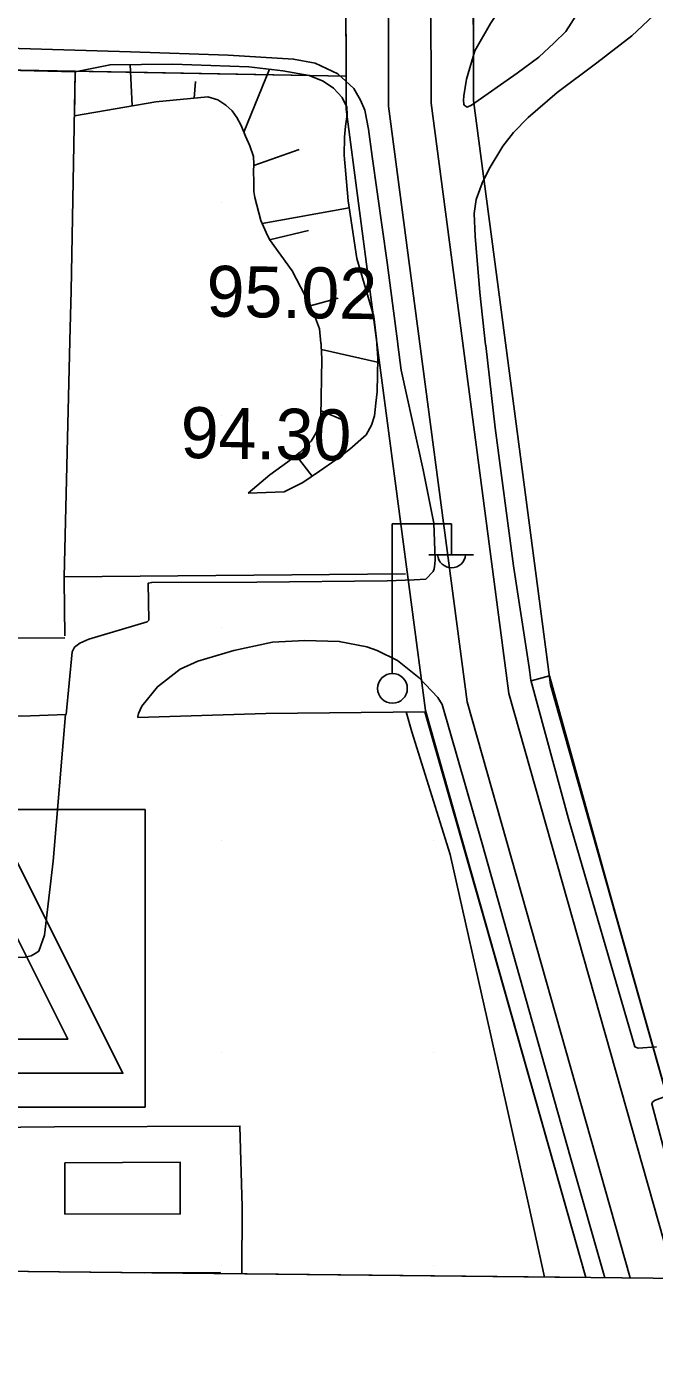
# Model space of a CAD drawing. Extents: x 417995 to 421451, y 4454518 to 4458015.
# Drawn here: x 420398.8 to 420472.7, y 4454999.4 to 4455155 of the extents above; entities that cross this region are included whole.
import ezdxf

# ---------------------------------------------------------------- set-up
doc = ezdxf.new("R2010")
doc.units = 0
for name, color, linetype in [('ADAKENARI', 7, 'Continuous'), ('B_Betonzemin', 7, 'Continuous'), ('B_Kapi', 7, 'Continuous'), ('B_Spor_Tesisleri', 7, 'Continuous'), ('KALDIRIM_FAT', 7, 'Continuous'), ('PAFTALAMA', 7, 'Continuous'), ('PL_AYA_PARK_DINLENME', 7, 'Continuous'), ('PL_EĞİTİM', 7, 'Continuous'), ('PL_KAMU_HİZMET_ALANI', 7, 'Continuous'), ('S_Elektrik_Diregi', 7, 'Continuous'), ('SEMBOL_FAT', 7, 'Continuous'), ('Sev_Sevalti', 7, 'Continuous'), ('Sev_Sevustu', 7, 'Continuous'), ('Sev_Tarama', 7, 'Continuous'), ('Sinir_Duvar_tek_tarafa_ait', 7, 'Continuous'), ('Sinir_Ist_Duvari', 7, 'Continuous'), ('Sinir_Tel_bir_taraf', 7, 'Continuous'), ('TRFAT_EĞİTİM', 7, 'Continuous'), ('TRFAT_PARKALANI', 7, 'Continuous'), ('Y_Kot_Noktasi', 7, 'Continuous'), ('Y_Lejant', 7, 'Continuous'), ('Yol_Kaldirim_kenari_bordurtasi', 7, 'Continuous'), ('Yol_Sose', 7, 'Continuous'), ('Yol_Toprak_Duz', 7, 'Continuous'), ('Yol_Toprak_Kesik', 7, 'Continuous')]:
    doc.layers.add(name, color=color, linetype=linetype)

msp = doc.modelspace()

# ---------------------------------------------------------------- linework, layer by layer
at = {"layer": 'ADAKENARI'}
for p, q in [((420451.44, 4455146.33), (420451.28, 4455217.73)), ((420436.41, 4455159.21), (420436.44, 4455149.21)), ((420315.15, 4455151.42), (420436.44, 4455149.21)), ((420436.44, 4455149.21), (420436.45, 4455145.33)), ((420436.45, 4455145.33), (420439.36, 4455123.19)), ((420454.49, 4455123.19), (420451.44, 4455146.33)), ((420439.36, 4455123.19), (420445.76, 4455074.56)), ((420460.48, 4455077.61), (420454.49, 4455123.19)), ((420480.29, 4455007.71), (420460.48, 4455077.61)), ((420445.76, 4455074.56), (420464.66, 4455007.88))]:
    msp.add_line(p, q, dxfattribs=at)
at = {"layer": 'B_Betonzemin'}
for points in [[(420403.4, 4455074.09), (420401.93, 4455056.87), (420400.94, 4455048.14), (420400.26, 4455046.28), (420399.84, 4455045.99), (420399.36, 4455045.7), (420398.67, 4455045.55), (420375.88, 4455045.37), (420375.61, 4455073.76)], [(420443.49, 4455074.4), (420444.17, 4455072.08), (420448.68, 4455057.65), (420453.42, 4455036.53), (420457.92, 4455016.5), (420459.8, 4455007.93)]]:
    msp.add_lwpolyline(points, dxfattribs=at)
at = {"layer": 'B_Kapi'}
msp.add_lwpolyline([(420403.34, 4455083.37), (420403.23, 4455089.9)], dxfattribs=at)
at = {"layer": 'B_Spor_Tesisleri'}
msp.add_lwpolyline([(420403.34, 4455015.33), (420403.33, 4455021.36), (420416.88, 4455021.45), (420416.9, 4455015.35)], close=True, dxfattribs=at)
msp.add_lwpolyline([(420412.71, 4455008.42), (420421.59, 4455008.48), (420421.59, 4455008.33)], dxfattribs=at)
at = {"layer": 'KALDIRIM_FAT'}
for p, q in [((420441.44, 4455145.66), (420441.28, 4455218.18)), ((420446.44, 4455146), (420446.28, 4455217.95)), ((420444.57, 4455121.88), (420441.44, 4455145.66)), ((420449.53, 4455122.54), (420446.44, 4455146)), ((420450.67, 4455075.58), (420444.57, 4455121.88)), ((420455.58, 4455076.59), (420449.53, 4455122.54)), ((420469.87, 4455007.82), (420450.67, 4455075.58)), ((420475.08, 4455007.77), (420455.58, 4455076.59))]:
    msp.add_line(p, q, dxfattribs=at)
at = {"layer": 'PAFTALAMA'}
msp.add_line((419138.44, 4455021.89), (421266.41, 4454999.4), dxfattribs=at)
at = {"layer": 'PL_AYA_PARK_DINLENME'}
msp.add_lwpolyline([(420323.63, 4455163.96), (420336.03, 4455233.44), (420344.03, 4455277.38), (420370.39, 4455328), (420388.66, 4455320.38), (420456.9, 4455291.9), (420456.9, 4455291.9), (420439.12, 4455249.29), (420436.28, 4455218.4), (420436.36, 4455181.21), (420436.41, 4455161.21), (420436.41, 4455159.21), (420436.44, 4455149.21), (420315.15, 4455151.42)], close=True, dxfattribs=at)
at = {"layer": 'PL_EĞİTİM'}
for p, q in [((420345.26, 4455009.14), (420464.66, 4455007.88)), ((420464.66, 4455007.88), (420345.26, 4455009.14))]:
    msp.add_line(p, q, dxfattribs=at)
msp.add_lwpolyline([(420464.66, 4455007.88), (420445.76, 4455074.56), (420439.36, 4455123.19), (420436.45, 4455145.33), (420436.44, 4455149.21), (420315.15, 4455151.42), (420296.75, 4455124.2), (420271.71, 4455086.83), (420279.66, 4455086.21), (420282.64, 4455090.54), (420329.76, 4455089.97), (420344.76, 4455089.79), (420345.26, 4455009.14)], dxfattribs=at)
at = {"layer": 'PL_KAMU_HİZMET_ALANI'}
msp.add_lwpolyline([(420608.01, 4455006.36), (420610.24, 4455191.26), (420611.77, 4455234.39), (420452.99, 4455236.3), (420451.28, 4455217.73), (420451.44, 4455146.33), (420454.49, 4455123.19), (420460.48, 4455077.61), (420480.29, 4455007.71)], dxfattribs=at)
at = {"layer": 'S_Elektrik_Diregi'}
for p, q in [((420441.85, 4455079.02), (420441.85, 4455096.52)), ((420441.85, 4455096.52), (420448.85, 4455096.52)), ((420448.85, 4455093.02), (420448.85, 4455096.52)), ((420446.19, 4455092.88), (420451.44, 4455092.88))]:
    msp.add_line(p, q, dxfattribs=at)
msp.add_circle((420441.89, 4455077.18), 1.75, dxfattribs=at)
msp.add_arc((420448.85, 4455093.03), 1.66, 184.8384, 355.1464, dxfattribs=at)
at = {"layer": 'SEMBOL_FAT'}
for p, q in [((420377.78, 4455062.91), (420412.78, 4455062.91)), ((420412.78, 4455062.91), (420412.78, 4455027.91)), ((420377.78, 4455027.91), (420412.78, 4455027.91))]:
    msp.add_line(p, q, dxfattribs=at)
msp.add_lwpolyline([(420395.28, 4455061.53), (420395.28, 4455052.61), (420386.89, 4455035.91), (420403.66, 4455035.91), (420395.28, 4455052.61), (420395.28, 4455061.53), (420410.15, 4455031.91), (420380.41, 4455031.91)], close=True, dxfattribs=at)
at = {"layer": 'Sev_Sevalti'}
for points in [[(420404.44, 4455144.51), (420404.53, 4455149.71), (420408.65, 4455150.54), (420416.03, 4455150.6), (420425, 4455150.31), (420428.98, 4455149.83), (420432.08, 4455149.27), (420433.74, 4455148.6), (420434.93, 4455147.78), (420435.97, 4455146.7), (420436.5, 4455145.55), (420436.54, 4455144.7), (420436.37, 4455143.32), (420436.25, 4455142.03), (420436.22, 4455139.91), (420436.69, 4455134.53), (420437.68, 4455127.74)], [(420437.68, 4455127.74), (420439.7, 4455120.92), (420440.02, 4455118.25), (420440.05, 4455117.72)], [(420440.06, 4455117.65), (420440.15, 4455116.02), (420440.1, 4455112.08), (420439.95, 4455110.71), (420439.78, 4455109.24), (420439.42, 4455108.16), (420438.78, 4455107.02), (420436.87, 4455105.31), (420435.21, 4455104.06), (420433.29, 4455102.74), (420431.34, 4455101.38), (420429.13, 4455100.31), (420424.91, 4455100.16)], [(420440.05, 4455117.72), (420440.06, 4455117.65)]]:
    msp.add_lwpolyline(points, dxfattribs=at)
at = {"layer": 'Sev_Sevustu'}
for points in [[(420433.47, 4455117.79), (420433.29, 4455119.48), (420432.82, 4455120.71), (420432.09, 4455122.45), (420430.09, 4455126.3), (420427.4, 4455129.97), (420427.01, 4455130.79), (420426.4, 4455132.23), (420425.7, 4455134.94), (420425.58, 4455135.64), (420425.57, 4455136.83), (420425.55, 4455137.93), (420425.56, 4455138.83), (420425.53, 4455139.75), (420425.08, 4455141), (420424.6, 4455142.12), (420424.08, 4455143.39), (420423.57, 4455144.35), (420423.02, 4455145.11), (420422.27, 4455145.8), (420421.34, 4455146.4), (420420.14, 4455146.75), (420414.05, 4455146.18), (420404.44, 4455144.51)], [(420424.91, 4455100.16), (420427.46, 4455102.29), (420429.57, 4455103.82), (420431.04, 4455104.96), (420432.32, 4455106.24), (420432.93, 4455107.31), (420433.47, 4455109.16), (420433.58, 4455115.91), (420433.5, 4455117.52), (420433.48, 4455117.72), (420433.47, 4455117.79)]]:
    msp.add_lwpolyline(points, dxfattribs=at)
at = {"layer": 'Sev_Tarama'}
for p, q in [((420411.24, 4455145.69), (420411.02, 4455150.56)), ((420424.4, 4455142.61), (420427.4, 4455150.02)), ((420418.56, 4455146.6), (420418.7, 4455148.55)), ((420425.56, 4455138.7), (420430.92, 4455140.57)), ((420426.55, 4455131.87), (420436.81, 4455133.71)), ((420427.41, 4455129.96), (420432.02, 4455131.05)), ((420432.21, 4455122.17), (420435.49, 4455123.1)), ((420433.53, 4455117.04), (420440.14, 4455115.57)), ((420433.48, 4455109.83), (420436.27, 4455108.67)), ((420430.56, 4455104.59), (420432.45, 4455102.15))]:
    msp.add_line(p, q, dxfattribs=at)
at = {"layer": 'Sinir_Duvar_tek_tarafa_ait'}
for points in [[(420328.79, 4455129.16), (420328.85, 4455151.54), (420404.53, 4455149.71), (420404.06, 4455123.96)], [(420404.06, 4455123.96), (420403.92, 4455118.1)], [(420403.34, 4455083.12), (420373.18, 4455082.92), (420344.61, 4455082.79), (420344.58, 4455089.9), (420328.97, 4455090.19), (420328.84, 4455118.82)], [(420403.92, 4455118.03), (420403.24, 4455090.31), (420403.23, 4455089.9)], [(420403.92, 4455118.1), (420403.92, 4455118.03)]]:
    msp.add_lwpolyline(points, dxfattribs=at)
at = {"layer": 'Sinir_Ist_Duvari'}
for points in [[(420443.43, 4455090.64), (420403.24, 4455090.31)], [(420445.7, 4455074.43), (420452.81, 4455049.64), (420464.64, 4455007.87)]]:
    msp.add_lwpolyline(points, dxfattribs=at)
at = {"layer": 'Sinir_Tel_bir_taraf'}
for points in [[(420346.07, 4455073.62), (420369.8, 4455073.69), (420390.78, 4455073.94), (420398.2, 4455073.89), (420403.49, 4455074.1)], [(420411.9, 4455073.74), (420426.99, 4455074.21), (420445.7, 4455074.43)]]:
    msp.add_lwpolyline(points, dxfattribs=at)
at = {"layer": 'TRFAT_EĞİTİM'}
for p, q in [((420421.71, 4455134.33), (420421.71, 4455134.33)), ((420421.71, 4455109.33), (420421.71, 4455109.33)), ((420421.71, 4455084.33), (420421.71, 4455084.33)), ((420421.71, 4455059.33), (420421.71, 4455059.33)), ((420446.71, 4455059.33), (420446.71, 4455059.33)), ((420421.71, 4455034.33), (420421.71, 4455034.33)), ((420446.71, 4455034.33), (420446.71, 4455034.33)), ((420421.71, 4455009.33), (420421.71, 4455009.33)), ((420446.71, 4455009.33), (420446.71, 4455009.33))]:
    msp.add_line(p, q, dxfattribs=at)
at = {"layer": 'TRFAT_PARKALANI'}
for p, q in [((420400.99, 4455153.17), (420400.99, 4455153.17)), ((420431.88, 4455149.48), (420431.88, 4455149.48))]:
    msp.add_line(p, q, dxfattribs=at)
at = {"layer": 'Y_Lejant'}
msp.add_lwpolyline([(419168.18, 4457798.01), (421295.36, 4457775.52), (421266.41, 4454999.4), (419138.44, 4455021.89)], close=True, dxfattribs=at)
at = {"layer": 'Yol_Kaldirim_kenari_bordurtasi'}
for points in [[(420472.59, 4455034.98), (420467.84, 4455051.8), (420460.39, 4455078.64), (420458.2, 4455078.08)], [(420424.14, 4455008.3), (420424.2, 4455016.2), (420423.94, 4455025.68), (420402.09, 4455025.61), (420374.43, 4455025.33), (420355.49, 4455025.39), (420355.57, 4455009.03)]]:
    msp.add_lwpolyline(points, dxfattribs=at)
at = {"layer": 'Yol_Sose'}
for points in [[(420456.13, 4455091.59), (420457.98, 4455079.65), (420458.18, 4455078.14)], [(420403.49, 4455074.1), (420404.17, 4455081.48), (420404.44, 4455082.01), (420405.08, 4455082.51), (420406.15, 4455082.96), (420413.02, 4455084.99), (420413.2, 4455085.21), (420413.14, 4455089.56), (420413.55, 4455089.65), (420425.94, 4455089.67), (420441.27, 4455089.81), (420444.44, 4455089.95), (420445.83, 4455090.01)], [(420466.88, 4455007.85), (420462.86, 4455022.01), (420452.41, 4455059.03), (420447.75, 4455075.28), (420447.25, 4455076.1), (420445.02, 4455078.42), (420442.48, 4455080.45), (420440.1, 4455081.62), (420438.86, 4455082.07), (420435.62, 4455082.7), (420431.59, 4455082.82), (420427.75, 4455082.61), (420423.21, 4455081.65), (420418.97, 4455080.39), (420416.9, 4455079.44), (420414.21, 4455077.36), (420412.39, 4455075.07), (420412, 4455074.23), (420411.92, 4455073.87), (420411.9, 4455073.74)], [(420458.18, 4455078.14), (420462.61, 4455061.83), (420470.43, 4455035.03), (420470.83, 4455034.87), (420472.97, 4455035)], [(420474.44, 4455029.32), (420472.74, 4455028.71), (420472.52, 4455028.5), (420472.44, 4455028.29), (420475.2, 4455017.82), (420477.88, 4455008.59), (420478.1, 4455007.73)]]:
    msp.add_lwpolyline(points, dxfattribs=at)
at = {"layer": 'Yol_Toprak_Duz'}
for points in [[(420460.56, 4455163.56), (420457.53, 4455161.05), (420455.68, 4455158.79), (420453.44, 4455155.4), (420451.57, 4455152.18), (420450.6, 4455148.86), (420450.3, 4455146.89), (420450.27, 4455146.33), (420450.31, 4455145.92)], [(420451.61, 4455130.37), (420451.51, 4455133.03), (420451.76, 4455134.67), (420452.44, 4455136.61), (420453.29, 4455138.31), (420454.87, 4455140.95), (420456.13, 4455142.55), (420457.87, 4455144.34), (420461.28, 4455147.28), (420465.95, 4455150.78), (420470.08, 4455153.94), (420472.61, 4455156.32)], [(420375.83, 4455153.87), (420387.11, 4455152.96), (420396.66, 4455152.5), (420411.07, 4455152.05), (420422.56, 4455151.65), (420430.25, 4455151.2), (420432.78, 4455150.74), (420435.46, 4455149.46), (420437.33, 4455147.75), (420438.12, 4455146.36), (420438.63, 4455145.21), (420439.05, 4455142.95), (420439.49, 4455139.74), (420441.28, 4455127.28)], [(420441.28, 4455127.28), (420442.53, 4455117.7)], [(420442.53, 4455117.7), (420442.54, 4455117.63)], [(420442.54, 4455117.63), (420442.93, 4455114.6), (420445.49, 4455102.88), (420446.76, 4455096.61), (420446.92, 4455092.35), (420446.87, 4455091.79), (420446.78, 4455091.24), (420446.69, 4455090.92), (420445.83, 4455090.01)]]:
    msp.add_lwpolyline(points, dxfattribs=at)
at = {"layer": 'Yol_Toprak_Kesik'}
for points in [[(420450.31, 4455145.92), (420450.32, 4455145.8), (420450.69, 4455145.56), (420451.18, 4455145.78), (420456.57, 4455149.55), (420459.12, 4455151.42), (420460.92, 4455153.12), (420462.31, 4455154.46), (420463.56, 4455156.4), (420465.55, 4455159.76), (420468.16, 4455163.22), (420469.12, 4455164.43), (420469.39, 4455165.05), (420469.4, 4455165.27), (420469.15, 4455165.88), (420469.08, 4455165.94)], [(420452.86, 4455117.59), (420452.16, 4455123.76), (420451.61, 4455130.37)], [(420452.87, 4455117.52), (420452.86, 4455117.59)], [(420456.13, 4455091.59), (420453.97, 4455107.82), (420452.87, 4455117.52)]]:
    msp.add_lwpolyline(points, dxfattribs=at)

# ---------------------------------------------------------------- texts
at = {"layer": 'Y_Kot_Noktasi'}
for s, p in [('95.02', (420419.96, 4455120.92)), ('94.30', (420416.92, 4455104.29))]:
    msp.add_text(s, height=6, rotation=359.0763, dxfattribs=at).set_placement(p)

doc.saveas('drawing.dxf')
